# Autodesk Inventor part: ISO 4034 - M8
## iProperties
Comments: To add or edit properties for Autodesk Inventor files, use iProperties.
Created: 2004-08
Part Number: ISO 4034 - M8
Vendor: Autodesk Inc.
Document SubType Name: Modeling
Designer: John Blackburn
Material: Default
Description: Hex Nut
Standard: ISO 4034
Size Designation: M8
Alert: To add or edit properties for Autodesk Inventor files, use iProperties.
Control State: 0
Master: False
Checked Out: False
Shininess: 64.0
Length Units: 11269
Angle Units: 11279
Time Units: 11290
Mass Units: 11283
Length Display Precision: 3
Angle Display Precision: 2
Compacted: True
EGR: 1
Density: 0.0
Volumn: 0.0
Area: 0.0
PropertySet Name: Model Information
Author: John Blackburn
Revision Number: 8
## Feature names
1. Body [Extrusion]
2. Chamfer1 [Revolution]
3. Thread [Hole]
4. Chamfer2
5. Chamfer3
